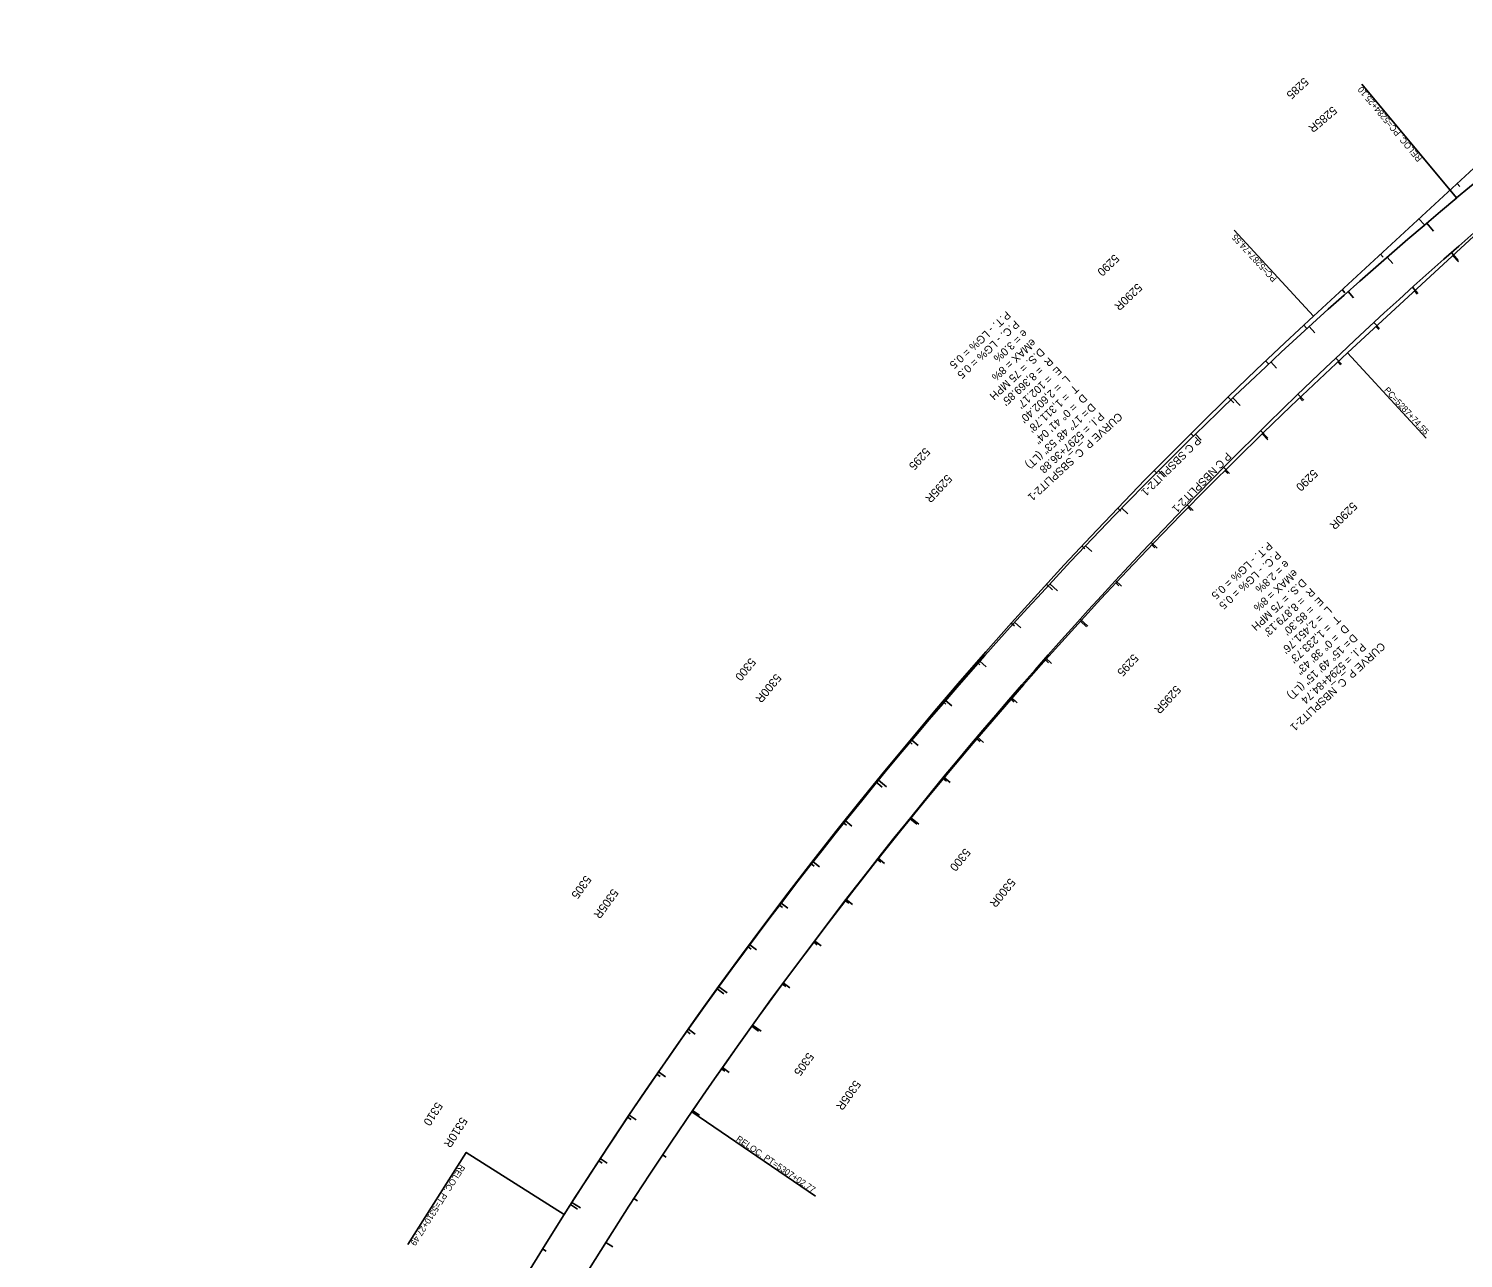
# Model space of a CAD drawing. Extents: x 2160877 to 2175861, y 601747 to 617724.
# Drawn here: x 2161211 to 2163959, y 604089 to 606444 of the extents above; entities that cross this region are included whole.
import ezdxf

# ---------------------------------------------------------------- set-up
doc = ezdxf.new("R2010")
doc.units = 0
for name, color, linetype in [('RD_HC_Cl', 7, 'Continuous'), ('RD_HC_CL_Rel', 7, 'Continuous'), ('RD_HC_Data', 7, 'Continuous'), ('RD_HC_Data_Rel', 7, 'Continuous'), ('RD_HC_Data_Tic', 7, 'Continuous'), ('RD_HC_Data_Tic_Rel', 7, 'Continuous'), ('RD_HC_TX_Rel_Sta50', 7, 'Continuous'), ('RD_HC_TX_StaOther', 7, 'Continuous')]:
    doc.layers.add(name, color=color, linetype=linetype)

msp = doc.modelspace()

# ---------------------------------------------------------------- linework, layer by layer
at = {"layer": 'RD_HC_Cl'}
for p, q in [((2172207.3, 613775.1), (2163672.2, 605893.8)), ((2172272.5, 613704.6), (2163737.4, 605823.3))]:
    msp.add_line(p, q, dxfattribs=at)
for radius in [8641.9, 8545.9]:
    msp.add_arc((2169535, 599544.7), radius, 132.71947, 164.41949, dxfattribs=at)
at = {"layer": 'RD_HC_CL_Rel'}
msp.add_line((2164335.8, 606444.4), (2163946.7, 606120.1), dxfattribs=at)
for centre, radius, end in [((2169810, 599356.6), 8879.1, 145.62858), ((2169305.2, 599690.4), 8369.8, 147.62243)]:
    msp.add_arc(centre, radius, 129.80773, end, dxfattribs=at)
at = {"layer": 'RD_HC_Data'}
for p, q in [((2163672.2, 605893.8), (2163520.1, 606058.6)), ((2163737.4, 605823.3), (2163888.4, 605659.7))]:
    msp.add_line(p, q, dxfattribs=at)
at = {"layer": 'RD_HC_Data_Rel'}
for p, q in [((2163946.7, 606120.1), (2163765.3, 606337.8)), ((2162481.2, 604369.4), (2162717.9, 604207.5))]:
    msp.add_line(p, q, dxfattribs=at)
msp.add_lwpolyline([(2162236.6, 604172.5), (2162048.9, 604291.4), (2161937, 604114.9)], dxfattribs=at)
at = {"layer": 'RD_HC_Data_Tic'}
for p, q in [((2163947.4, 606147.9), (2163952.8, 606142)), ((2163873.9, 606080.1), (2163884.8, 606068.3)), ((2163800.5, 606012.2), (2163805.9, 606006.4)), ((2163939.1, 606009.5), (2163949.9, 605997.8)), ((2163727, 605944.4), (2163732.4, 605938.5)), ((2163865.6, 605941.7), (2163871, 605935.8)), ((2163653.6, 605876.5), (2163659, 605870.7)), ((2163792.1, 605873.9), (2163797.6, 605868)), ((2163580.7, 605808), (2163586.2, 605802.3)), ((2163718.7, 605806), (2163724.1, 605800.1)), ((2163508.6, 605738.7), (2163519.8, 605727.3)), ((2163645.8, 605737.5), (2163651.3, 605731.7)), ((2163437.4, 605668.6), (2163443, 605662.9)), ((2163573.8, 605668.2), (2163584.9, 605656.7)), ((2163366.9, 605597.6), (2163372.6, 605592)), ((2163502.5, 605598), (2163508.2, 605592.3)), ((2163297.3, 605525.8), (2163303, 605520.3)), ((2163432.1, 605527), (2163437.8, 605521.4)), ((2163228.5, 605453.3), (2163234.3, 605447.8)), ((2163362.5, 605455.2), (2163368.3, 605449.6)), ((2163160.5, 605379.9), (2163172.3, 605369.1)), ((2163293.8, 605382.6), (2163299.6, 605377.1)), ((2163093.4, 605305.7), (2163099.4, 605300.4)), ((2163225.9, 605309.1), (2163237.7, 605298.3)), ((2163027.2, 605230.8), (2163033.2, 605225.6)), ((2163158.9, 605234.9), (2163164.9, 605229.6)), ((2162961.9, 605155.1), (2162967.9, 605149.9)), ((2163092.7, 605159.9), (2163098.8, 605154.7)), ((2162897.4, 605078.7), (2162903.5, 605073.6)), ((2163027.5, 605084.1), (2163033.6, 605079)), ((2162833.8, 605001.5), (2162846.2, 604991.4)), ((2162963.1, 605007.6), (2162969.3, 605002.5)), ((2162899.6, 604930.3), (2162912.1, 604920.3)), ((2162771.1, 604923.6), (2162777.4, 604918.6)), ((2162837.1, 604852.3), (2162843.3, 604847.4)), ((2162709.3, 604845), (2162715.6, 604840.1)), ((2162648.4, 604765.7), (2162654.8, 604760.8)), ((2162775.4, 604773.6), (2162781.8, 604768.7)), ((2162588.5, 604685.6), (2162594.9, 604680.9)), ((2162714.7, 604694.1), (2162721.1, 604689.3)), ((2162529.5, 604604.9), (2162542.4, 604595.5)), ((2162654.9, 604614), (2162661.4, 604609.2)), ((2162471.4, 604523.5), (2162477.9, 604518.9)), ((2162596.1, 604533.1), (2162609.1, 604523.8)), ((2162414.2, 604441.4), (2162420.8, 604436.9)), ((2162538.2, 604451.6), (2162544.7, 604447)), ((2162358.1, 604358.7), (2162364.7, 604354.2)), ((2162481.2, 604369.4), (2162487.8, 604364.9)), ((2162302.8, 604275.3), (2162309.5, 604271)), ((2162425.3, 604286.5), (2162431.9, 604282.1)), ((2162248.6, 604191.3), (2162262.1, 604182.7)), ((2162370.3, 604203), (2162377, 604198.6)), ((2162195.3, 604106.7), (2162202.1, 604102.5)), ((2162316.3, 604118.8), (2162329.8, 604110.3))]:
    msp.add_line(p, q, dxfattribs=at)
at = {"layer": 'RD_HC_Data_Tic_Rel'}
for p, q in [((2163889.4, 606071.9), (2163902.4, 606056.7)), ((2163813.6, 606006.8), (2163824.1, 605994.7)), ((2163936.5, 606015.5), (2163949.7, 606000.5)), ((2163861.9, 605948.9), (2163872.6, 605937)), ((2163738.5, 605940.7), (2163749.1, 605928.7)), ((2163664.2, 605873.7), (2163675, 605861.9)), ((2163788, 605881.5), (2163798.8, 605869.7)), ((2163714.9, 605813.3), (2163725.9, 605801.6)), ((2163590.7, 605805.9), (2163601.7, 605794.2)), ((2163518.1, 605737.2), (2163531.9, 605722.7)), ((2163642.6, 605744.2), (2163653.7, 605732.7)), ((2163571, 605674.4), (2163585.1, 605660.1)), ((2163446.2, 605667.6), (2163457.4, 605656.2)), ((2163375.3, 605597.2), (2163386.6, 605585.9)), ((2163500.3, 605603.7), (2163511.6, 605592.4)), ((2163305.1, 605525.9), (2163316.6, 605514.8)), ((2163430.3, 605532.2), (2163441.8, 605521.1)), ((2163235.8, 605453.8), (2163247.4, 605442.8)), ((2163361.2, 605460), (2163372.8, 605449)), ((2163167.4, 605380.9), (2163182.1, 605367.3)), ((2163292.8, 605387), (2163304.6, 605376.1)), ((2163225.3, 605313.2), (2163240.2, 605299.8)), ((2163099.8, 605307.2), (2163111.7, 605296.4)), ((2163033.2, 605232.6), (2163045.2, 605222)), ((2163158.7, 605238.7), (2163170.7, 605228.1)), ((2162967.4, 605157.3), (2162979.5, 605146.8)), ((2163092.8, 605163.4), (2163104.9, 605152.9)), ((2162902.6, 605081.2), (2162914.8, 605070.9)), ((2163027.9, 605087.4), (2163040.1, 605077)), ((2162963.8, 605010.6), (2162976.1, 605000.4)), ((2162838.6, 605004.3), (2162854.1, 604991.6)), ((2162900.5, 604933.1), (2162916.1, 604920.6)), ((2162775.6, 604926.7), (2162788.1, 604916.7)), ((2162713.5, 604848.3), (2162726.1, 604838.4)), ((2162838.2, 604855), (2162850.7, 604845.1)), ((2162652.3, 604769.2), (2162665.1, 604759.4)), ((2162776.7, 604776.1), (2162789.3, 604766.3)), ((2162592.1, 604689.3), (2162605, 604679.8)), ((2162716.1, 604696.6), (2162728.9, 604686.9)), ((2162532.9, 604608.7), (2162549.1, 604597)), ((2162656.4, 604616.3), (2162669.3, 604606.9)), ((2162474.6, 604527.5), (2162487.7, 604518.2)), ((2162597.6, 604535.4), (2162613.9, 604523.8)), ((2162417.3, 604445.5), (2162430.5, 604436.4)), ((2162539.7, 604453.9), (2162552.8, 604444.7)), ((2162361, 604362.9), (2162374.3, 604354)), ((2162482.8, 604371.7), (2162496, 604362.6)), ((2162305.7, 604279.6), (2162319, 604270.8)), ((2162251.3, 604195.6), (2162268.2, 604184.9))]:
    msp.add_line(p, q, dxfattribs=at)

# ---------------------------------------------------------------- texts
at = {"layer": 'RD_HC_Data'}
for rotation, p in [(132.7195, (2163602.9, 605965.9)), (312.7195, (2163806.7, 605751.2))]:
    msp.add_text('PC=5287+74.55', height=12, rotation=rotation, dxfattribs=at).set_placement(p)
at = {"layer": 'RD_HC_Data_Rel'}
for s, height, rotation, p in [('RELOC. PC=5284+25.10', 12, 129.8077, (2163881.2, 606195.7)), ('P.T. - LG% = 0.5', 15, 222.7195, (2163083.9, 605904.2)), ('P.C. - LG% = 0.5', 15, 222.7195, (2163100.2, 605886.6)), ('e = 3.0%', 15, 222.7195, (2163116.5, 605869)), ('eMAX = 8%', 15, 222.7195, (2163132.7, 605851.3)), ('D.S. = 75 MPH', 15, 222.7195, (2163149, 605833.7)), ("R  = 8,369.85'", 15, 222.7195, (2163165.3, 605816.1)), ("E  = 102.17'", 15, 222.7195, (2163181.6, 605798.4)), ("L  = 2,602.40'", 15, 222.7195, (2163197.9, 605780.8)), ("T  = 1,311.78'", 15, 222.7195, (2163214.1, 605763.2)), ('D  = 0%%d 41\' 04"', 15, 222.7195, (2163230.4, 605745.5)), ('D ', 15, 222.7195, (2163246.7, 605727.9)), ('   = 17%%d 48\' 53" (LT)', 15, 222.7195, (2163246.7, 605727.9)), ('CURVE P_C_SBSPLIT2-1', 15, 222.7195, (2163298, 605710)), ('P.I. = 5297+36.88', 15, 222.7195, (2163263, 605710.3)), ('P C SBSPLIT2-1', 15, 224.5304, (2163448.1, 605663.6)), ('P C NBSPLIT2-1', 15, 225.4895, (2163506.1, 605633.9)), ('P.T. - LG% = 0.5', 15, 222.7195, (2163585.5, 605462.3)), ('P.C. - LG% = 0.5', 15, 222.7195, (2163601.8, 605444.6)), ('e = 2.8%', 15, 222.7195, (2163618.1, 605427)), ('eMAX = 8%', 15, 222.7195, (2163634.4, 605409.4)), ('D.S. = 75 MPH', 15, 222.7195, (2163650.7, 605391.7)), ("R  = 8,879.13'", 15, 222.7195, (2163666.9, 605374.1)), ("E  = 85.30'", 15, 222.7195, (2163683.2, 605356.5)), ("L  = 2,451.76'", 15, 222.7195, (2163699.5, 605338.8)), ("T  = 1,233.73'", 15, 222.7195, (2163715.8, 605321.2)), ('D  = 0%%d 38\' 43"', 15, 222.7195, (2163732.1, 605303.6)), ('   = 15%%d 49\' 15" (LT)', 15, 222.7195, (2163748.4, 605286)), ('CURVE P_C_NBSPLIT2-1', 15, 222.7195, (2163801.6, 605269.8)), ('P.I. = 5294+84.74', 15, 222.7195, (2163764.6, 605268.3)), ('D ', 15, 222.7195, (2163748.4, 605286)), ('RELOC. PT=5307+02.77', 12, 325.6286, (2162564.9, 604314.6)), ('RELOC. PT=5310+27.49', 12, 237.6224, (2162037.5, 604269.1))]:
    msp.add_text(s, height=height, rotation=rotation, dxfattribs=at).set_placement(p)
at = {"layer": 'RD_HC_TX_Rel_Sta50'}
for s, rotation, p in [('5285R', 220.3205, (2163709.1, 606296.9)), ('5290R', 223.7432, (2163335, 605957.8)), ('5295R', 227.166, (2162969.9, 605591.5)), ('5290R', 224.6408, (2163746.8, 605538.7)), ('5300R', 230.5887, (2162642.1, 605209.9)), ('5295R', 227.8673, (2163408.2, 605187.4)), ('5305R', 234.0115, (2162329.1, 604797.8)), ('5300R', 231.0937, (2163090.4, 604818.1)), ('5305R', 234.3201, (2162793.5, 604431)), ('5310R', 237.4342, (2162039.1, 604360.3))]:
    msp.add_text(s, height=16, rotation=rotation, dxfattribs=at).set_placement(p)
at = {"layer": 'RD_HC_TX_StaOther'}
for s, rotation, p in [('5285', 222.7195, (2163654.1, 606351.9)), ('5290', 224.2142, (2163290.9, 606013.4)), ('5295', 227.5292, (2162927.9, 605643)), ('5290', 224.231, (2163671.4, 605601.3)), ('5300', 230.8442, (2162593.1, 605240.1)), ('5295', 227.5832, (2163327, 605247.7)), ('5300', 230.9354, (2163004.4, 604875.4)), ('5305', 234.1592, (2162277.2, 604823.4)), ('5305', 234.2877, (2162703.6, 604484)), ('5310', 237.4741, (2161991.7, 604389.2))]:
    msp.add_text(s, height=16, rotation=rotation, dxfattribs=at).set_placement(p)

doc.saveas('drawing.dxf')
